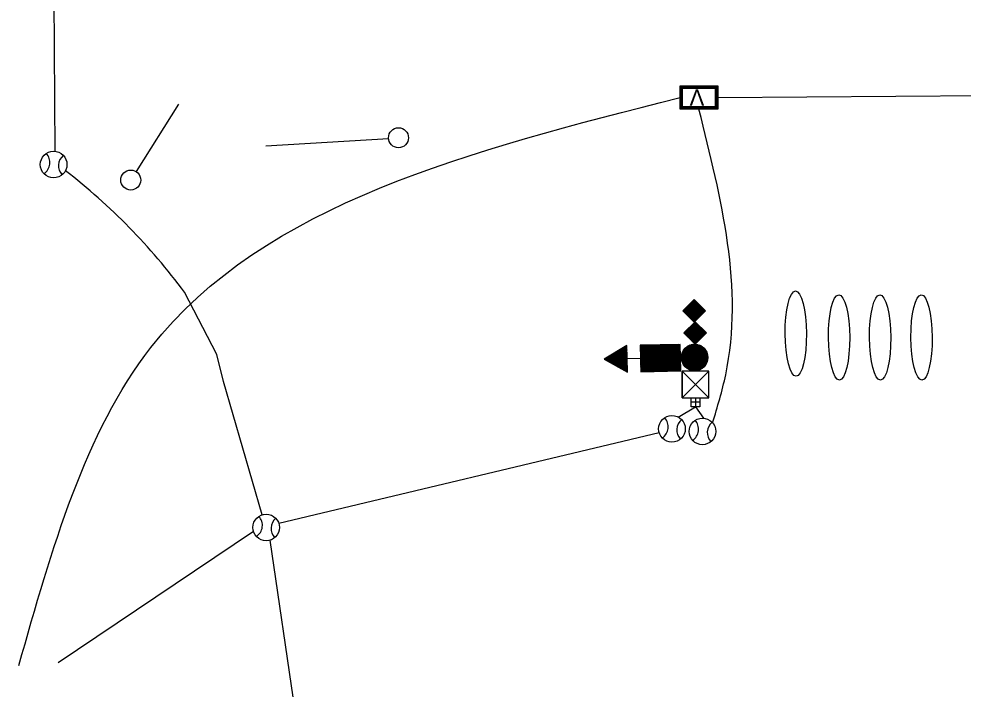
# Model space of a CAD drawing. Extents: x 584850 to 602551, y 145475 to 158627.
# Drawn here: x 594064.4 to 594348.1, y 154200.4 to 154401.9 of the extents above; entities that cross this region are included whole.
import ezdxf

# ---------------------------------------------------------------- set-up
doc = ezdxf.new("R2010")
doc.units = 0
for name, color, linetype in [('B_MISC', 7, 'Continuous'), ('Default', 7, 'Continuous'), ('E_RDWY', 7, 'Continuous')]:
    doc.layers.add(name, color=color, linetype=linetype)

# ---------------------------------------------------------------- blocks, each defined once
blk = doc.blocks.new('PB24X42')
at = {"layer": 'E_RDWY'}
blk.add_circle((0, 0), 2, dxfattribs=at)
for centre, start, end in [((-2.59, 0.09), 308.3742, 47.6044), ((2.73, 0.07), 134.4184, 228.4474)]:
    blk.add_arc(centre, 2, start, end, dxfattribs=at)

msp = doc.modelspace()

# ---------------------------------------------------------------- linework, layer by layer
at = {"layer": 'B_MISC'}
for p, q in [((594074.49, 154479.93), (594075.15, 154362.09)), ((594274.39, 154378.27), (594437.1, 154379.42)), ((594123.87, 154301.05), (594114.16, 154319.71)), ((594125.91, 154292.88), (594123.87, 154301.05)), ((594137.5, 154252.82), (594125.91, 154292.88)), ((594262.48, 154282.2), (594267.68, 154285.29)), ((594267.68, 154285.29), (594270.14, 154281.87)), ((594256.83, 154277.44), (594142.52, 154250.21)), ((594134.89, 154247.8), (594076.18, 154208.26)), ((594194.8, 153867.11), (594139.91, 154245.19))]:
    msp.add_line(p, q, dxfattribs=at)
msp.add_arc((593965.3, 154209.77), 185.05, 36.4483, 52.3419, dxfattribs=at)
for points in [[(594064.37, 154207.47), (594104.06, 154303.13), (594263.09, 154378.27)], [(594272.86, 154280.46), (594276.79, 154294.91), (594268.74, 154374.75)]]:
    msp.add_spline(points, degree=3, dxfattribs=at)
at = {"layer": 'Default'}
for p, q in [((594112.38, 154376.3), (594099.59, 154355.99)), ((594138.54, 154363.7), (594175.47, 154365.99))]:
    msp.add_line(p, q, dxfattribs=at)
for centre in [(594178.46, 154366.18), (594097.99, 154353.46)]:
    msp.add_circle(centre, 3, dxfattribs=at)
at = {"layer": 'E_RDWY'}
for p, q in [((594265.56, 154315.83), (594265.56, 154312.5)), ((594265.56, 154315.83), (594269.01, 154315.83)), ((594265.84, 154316.12), (594265.84, 154312.21)), ((594265.84, 154316.12), (594268.72, 154316.12)), ((594266.13, 154316.41), (594266.13, 154311.93)), ((594266.13, 154316.41), (594268.44, 154316.41)), ((594266.42, 154316.7), (594266.42, 154311.64)), ((594266.42, 154316.7), (594268.15, 154316.7)), ((594266.71, 154316.99), (594266.71, 154311.35)), ((594266.71, 154316.99), (594267.86, 154316.99)), ((594267, 154317.27), (594267, 154311.06)), ((594267, 154317.27), (594267.57, 154317.27)), ((594267.28, 154317.56), (594267.28, 154310.77)), ((594267.57, 154317.27), (594267.57, 154311.06)), ((594267.86, 154316.99), (594267.86, 154311.35)), ((594268.15, 154316.7), (594268.15, 154311.64)), ((594268.44, 154316.41), (594268.44, 154311.93)), ((594268.72, 154316.12), (594268.72, 154312.21)), ((594269.01, 154315.83), (594269.01, 154312.5)), ((594263.95, 154314.11), (594270.62, 154314.11)), ((594264.12, 154314.39), (594264.12, 154313.94)), ((594264.12, 154314.39), (594270.45, 154314.39)), ((594264.24, 154313.82), (594270.33, 154313.82)), ((594264.4, 154314.68), (594264.4, 154313.65)), ((594264.4, 154314.68), (594270.16, 154314.68)), ((594264.53, 154313.53), (594270.04, 154313.53)), ((594264.69, 154314.97), (594264.69, 154313.37)), ((594264.69, 154314.97), (594269.88, 154314.97)), ((594264.82, 154313.24), (594269.75, 154313.24)), ((594264.98, 154315.26), (594264.98, 154313.08)), ((594264.98, 154315.26), (594269.59, 154315.26)), ((594265.1, 154312.95), (594269.46, 154312.95)), ((594265.27, 154315.55), (594265.27, 154312.79)), ((594265.27, 154315.55), (594269.3, 154315.55)), ((594269.3, 154315.55), (594269.3, 154312.79)), ((594269.59, 154315.26), (594269.59, 154313.08)), ((594269.88, 154314.97), (594269.88, 154313.37)), ((594270.16, 154314.68), (594270.16, 154313.65)), ((594270.45, 154314.39), (594270.45, 154313.94)), ((594265.39, 154312.67), (594269.18, 154312.67)), ((594265.68, 154312.38), (594268.89, 154312.38)), ((594265.97, 154312.09), (594268.6, 154312.09)), ((594266.26, 154311.8), (594268.31, 154311.8)), ((594266.54, 154311.51), (594268.02, 154311.51)), ((594266.71, 154310), (594266.71, 154304.94)), ((594266.71, 154310), (594268.44, 154310)), ((594266.83, 154311.23), (594267.74, 154311.23)), ((594267, 154310.29), (594267, 154304.65)), ((594267, 154310.29), (594268.15, 154310.29)), ((594267.12, 154310.94), (594267.45, 154310.94)), ((594267.28, 154310.58), (594267.28, 154304.37)), ((594267.28, 154310.58), (594267.86, 154310.58)), ((594267.57, 154310.87), (594267.57, 154304.08)), ((594267.86, 154310.58), (594267.86, 154304.37)), ((594268.15, 154310.29), (594268.15, 154304.65)), ((594268.44, 154310), (594268.44, 154304.94)), ((594264.24, 154307.41), (594270.9, 154307.41)), ((594264.4, 154307.7), (594264.4, 154307.25)), ((594264.4, 154307.7), (594270.74, 154307.7)), ((594264.69, 154307.99), (594264.69, 154306.96)), ((594264.69, 154307.99), (594270.45, 154307.99)), ((594264.98, 154308.28), (594264.98, 154306.67)), ((594264.98, 154308.28), (594270.16, 154308.28)), ((594265.27, 154308.56), (594265.27, 154306.38)), ((594265.27, 154308.56), (594269.88, 154308.56)), ((594265.56, 154308.85), (594265.56, 154306.09)), ((594265.56, 154308.85), (594269.59, 154308.85)), ((594265.84, 154309.14), (594265.84, 154305.81)), ((594265.84, 154309.14), (594269.3, 154309.14)), ((594266.13, 154309.43), (594266.13, 154305.52)), ((594266.13, 154309.43), (594269.01, 154309.43)), ((594266.42, 154309.72), (594266.42, 154305.23)), ((594266.42, 154309.72), (594268.72, 154309.72)), ((594268.72, 154309.72), (594268.72, 154305.23)), ((594269.01, 154309.43), (594269.01, 154305.52)), ((594269.3, 154309.14), (594269.3, 154305.81)), ((594269.59, 154308.85), (594269.59, 154306.09)), ((594269.88, 154308.56), (594269.88, 154306.38)), ((594270.16, 154308.28), (594270.16, 154306.67)), ((594270.45, 154307.99), (594270.45, 154306.96)), ((594270.74, 154307.7), (594270.74, 154307.25)), ((594264.53, 154307.12), (594270.62, 154307.12)), ((594264.82, 154306.84), (594270.33, 154306.84)), ((594265.1, 154306.55), (594270.04, 154306.55)), ((594265.39, 154306.26), (594269.75, 154306.26)), ((594265.68, 154305.97), (594269.46, 154305.97)), ((594265.97, 154305.68), (594269.18, 154305.68)), ((594266.26, 154305.4), (594268.89, 154305.4)), ((594266.54, 154305.11), (594268.6, 154305.11)), ((594266.83, 154304.82), (594268.31, 154304.82)), ((594267.12, 154304.53), (594268.02, 154304.53)), ((594241.16, 154299.08), (594243.46, 154301.48)), ((594241.38, 154298.96), (594244.26, 154301.96)), ((594241.6, 154298.84), (594245.05, 154302.44)), ((594241.81, 154298.72), (594245.85, 154302.92)), ((594242.03, 154298.61), (594246.64, 154303.41)), ((594242.25, 154298.49), (594247.1, 154303.54)), ((594242.47, 154298.37), (594247.11, 154303.2)), ((594242.68, 154298.25), (594247.12, 154302.86)), ((594242.9, 154298.13), (594247.12, 154302.52)), ((594243.12, 154298.01), (594247.13, 154302.18)), ((594243.34, 154297.89), (594247.14, 154301.85)), ((594247.22, 154297.9), (594243.48, 154301.49)), ((594243.55, 154297.77), (594247.15, 154301.51)), ((594247.21, 154298.24), (594243.69, 154301.62)), ((594247.2, 154298.58), (594243.9, 154301.75)), ((594247.2, 154298.92), (594244.12, 154301.88)), ((594247.19, 154299.26), (594244.33, 154302.01)), ((594247.18, 154299.6), (594244.54, 154302.14)), ((594247.18, 154299.94), (594244.75, 154302.26)), ((594247.17, 154300.28), (594244.97, 154302.39)), ((594247.16, 154300.62), (594245.18, 154302.52)), ((594247.16, 154300.96), (594245.39, 154302.65)), ((594247.15, 154301.3), (594245.6, 154302.78)), ((594247.14, 154301.64), (594245.82, 154302.91)), ((594247.14, 154301.97), (594246.03, 154303.04)), ((594247.13, 154302.31), (594246.24, 154303.17)), ((594247.12, 154302.65), (594246.46, 154303.29)), ((594247.11, 154302.99), (594246.67, 154303.42)), ((594247.11, 154303.33), (594246.88, 154303.55)), ((594247.1, 154303.67), (594247.09, 154303.68)), ((594251.1, 154303.61), (594251.29, 154303.81)), ((594259.07, 154295.96), (594251.1, 154303.61)), ((594251.11, 154303.27), (594251.63, 154303.81)), ((594258.73, 154295.96), (594251.11, 154303.27)), ((594251.12, 154302.59), (594252.31, 154303.83)), ((594251.12, 154302.93), (594251.97, 154303.82)), ((594258.39, 154295.95), (594251.12, 154302.93)), ((594258.05, 154295.94), (594251.12, 154302.59)), ((594251.13, 154302.25), (594252.65, 154303.83)), ((594257.71, 154295.94), (594251.13, 154302.25)), ((594251.14, 154301.57), (594253.33, 154303.85)), ((594251.14, 154301.91), (594252.99, 154303.84)), ((594257.37, 154295.93), (594251.14, 154301.91)), ((594257.03, 154295.92), (594251.14, 154301.57)), ((594251.15, 154301.23), (594253.67, 154303.86)), ((594251.16, 154300.56), (594254.35, 154303.87)), ((594251.16, 154300.89), (594254.01, 154303.86)), ((594251.17, 154300.22), (594254.69, 154303.88)), ((594251.18, 154299.88), (594255.02, 154303.88)), ((594251.19, 154299.2), (594255.7, 154303.9)), ((594251.19, 154299.54), (594255.36, 154303.89)), ((594251.2, 154298.86), (594256.04, 154303.9)), ((594251.21, 154298.18), (594256.72, 154303.92)), ((594251.21, 154298.52), (594256.38, 154303.91)), ((594251.22, 154297.84), (594257.06, 154303.92)), ((594251.23, 154297.16), (594257.74, 154303.94)), ((594251.23, 154297.5), (594257.4, 154303.93)), ((594251.24, 154296.82), (594258.08, 154303.95)), ((594259.41, 154295.97), (594251.24, 154303.81)), ((594251.25, 154296.14), (594258.76, 154303.96)), ((594251.25, 154296.48), (594258.42, 154303.95)), ((594251.26, 154295.8), (594259.1, 154303.97)), ((594259.75, 154295.98), (594251.58, 154303.81)), ((594251.6, 154295.81), (594259.44, 154303.97)), ((594260.08, 154295.98), (594251.92, 154303.82)), ((594251.94, 154295.82), (594259.78, 154303.98)), ((594260.42, 154295.99), (594252.26, 154303.83)), ((594252.28, 154295.83), (594260.11, 154303.99)), ((594260.76, 154296), (594252.6, 154303.83)), ((594252.62, 154295.83), (594260.45, 154303.99)), ((594261.1, 154296.01), (594252.94, 154303.84)), ((594252.96, 154295.84), (594260.79, 154304)), ((594261.44, 154296.01), (594253.28, 154303.85)), ((594253.3, 154295.85), (594261.13, 154304.01)), ((594261.78, 154296.02), (594253.62, 154303.85)), ((594253.64, 154295.85), (594261.47, 154304.01)), ((594262.12, 154296.03), (594253.96, 154303.86)), ((594253.98, 154295.86), (594261.81, 154304.02)), ((594262.46, 154296.03), (594254.3, 154303.87)), ((594254.32, 154295.87), (594262.15, 154304.03)), ((594262.8, 154296.04), (594254.64, 154303.88)), ((594254.66, 154295.87), (594262.49, 154304.04)), ((594263.14, 154296.05), (594254.98, 154303.88)), ((594254.99, 154295.88), (594262.83, 154304.04)), ((594263.26, 154296.27), (594255.32, 154303.89)), ((594255.33, 154295.89), (594263.1, 154303.98)), ((594263.25, 154296.61), (594255.66, 154303.9)), ((594255.67, 154295.89), (594263.11, 154303.64)), ((594263.24, 154296.95), (594256, 154303.9)), ((594256.01, 154295.9), (594263.11, 154303.3)), ((594263.23, 154297.29), (594256.33, 154303.91)), ((594256.35, 154295.91), (594263.12, 154302.96)), ((594263.23, 154297.63), (594256.67, 154303.92)), ((594256.69, 154295.92), (594263.13, 154302.62)), ((594263.22, 154297.96), (594257.01, 154303.92)), ((594257.03, 154295.92), (594263.13, 154302.28)), ((594263.21, 154298.3), (594257.35, 154303.93)), ((594257.37, 154295.93), (594263.14, 154301.94)), ((594263.21, 154298.64), (594257.69, 154303.94)), ((594257.71, 154295.94), (594263.15, 154301.6)), ((594263.2, 154298.98), (594258.03, 154303.94)), ((594263.19, 154299.32), (594258.37, 154303.95)), ((594263.19, 154299.66), (594258.71, 154303.96)), ((594263.18, 154300), (594259.05, 154303.97)), ((594263.17, 154300.34), (594259.39, 154303.97)), ((594263.17, 154300.68), (594259.73, 154303.98)), ((594263.16, 154301.02), (594260.07, 154303.99)), ((594263.15, 154301.36), (594260.41, 154303.99)), ((594263.14, 154301.7), (594260.75, 154304)), ((594263.14, 154302.04), (594261.09, 154304.01)), ((594263.13, 154302.38), (594261.42, 154304.01)), ((594263.12, 154302.72), (594261.76, 154304.02)), ((594263.12, 154303.05), (594262.1, 154304.03)), ((594263.11, 154303.39), (594262.44, 154304.03)), ((594263.1, 154303.73), (594262.78, 154304.04)), ((594263.46, 154300.12), (594267.29, 154304.11)), ((594263.48, 154299.79), (594267.62, 154304.1)), ((594263.48, 154300.49), (594266.92, 154304.07)), ((594263.51, 154299.47), (594267.93, 154304.08)), ((594263.53, 154300.88), (594266.52, 154303.99)), ((594263.58, 154299.2), (594268.22, 154304.03)), ((594263.64, 154298.92), (594268.49, 154303.97)), ((594263.67, 154301.37), (594266.06, 154303.87)), ((594263.74, 154298.67), (594268.75, 154303.9)), ((594269.15, 154296.5), (594263.77, 154301.66)), ((594263.84, 154298.43), (594268.99, 154303.8)), ((594269.37, 154296.62), (594263.88, 154301.88)), ((594263.93, 154302), (594265.45, 154303.58)), ((594263.95, 154298.2), (594269.22, 154303.69)), ((594269.58, 154296.74), (594263.99, 154302.11)), ((594264.08, 154297.99), (594269.44, 154303.58)), ((594269.79, 154296.88), (594264.13, 154302.31)), ((594264.22, 154297.78), (594269.65, 154303.44)), ((594269.98, 154297.03), (594264.27, 154302.51)), ((594264.36, 154297.59), (594269.85, 154303.31)), ((594270.16, 154297.19), (594264.41, 154302.71)), ((594264.52, 154297.41), (594270.04, 154303.16)), ((594270.33, 154297.35), (594264.58, 154302.88)), ((594264.69, 154297.24), (594270.21, 154302.99)), ((594270.49, 154297.54), (594264.75, 154303.05)), ((594264.87, 154297.08), (594270.39, 154302.83)), ((594270.65, 154297.72), (594264.92, 154303.21)), ((594265.06, 154296.93), (594270.54, 154302.64)), ((594270.78, 154297.92), (594265.12, 154303.35)), ((594265.25, 154296.78), (594270.69, 154302.45)), ((594270.91, 154298.13), (594265.32, 154303.49)), ((594265.47, 154296.66), (594270.83, 154302.25)), ((594271.03, 154298.34), (594265.54, 154303.62)), ((594265.69, 154296.54), (594270.95, 154302.03)), ((594271.13, 154298.58), (594265.77, 154303.73)), ((594265.91, 154296.43), (594271.07, 154301.8)), ((594271.23, 154298.82), (594266, 154303.84)), ((594266.16, 154296.35), (594271.17, 154301.57)), ((594271.31, 154299.08), (594266.26, 154303.92)), ((594271.37, 154299.36), (594266.53, 154304)), ((594271.42, 154299.64), (594266.81, 154304.06)), ((594271.44, 154299.95), (594267.13, 154304.09)), ((594267.41, 154304.24), (594267.74, 154304.24)), ((594271.44, 154300.28), (594267.45, 154304.11)), ((594271.4, 154300.65), (594267.82, 154304.09)), ((594271.35, 154301.04), (594268.23, 154304.03)), ((594271.19, 154301.52), (594268.69, 154303.92)), ((594270.89, 154302.14), (594269.31, 154303.66)), ((594240.29, 154299.56), (594240.29, 154299.56)), ((594241.1, 154299.12), (594240.5, 154299.69)), ((594240.51, 154299.44), (594241.08, 154300.04)), ((594241.92, 154298.67), (594240.72, 154299.82)), ((594240.73, 154299.32), (594241.88, 154300.52)), ((594242.73, 154298.22), (594240.93, 154299.95)), ((594240.94, 154299.2), (594242.67, 154301)), ((594243.54, 154297.77), (594241.14, 154300.08)), ((594244.36, 154297.32), (594241.35, 154300.21)), ((594245.17, 154296.88), (594241.57, 154300.34)), ((594245.98, 154296.43), (594241.78, 154300.46)), ((594246.79, 154295.98), (594241.99, 154300.59)), ((594247.26, 154295.87), (594242.2, 154300.72)), ((594247.25, 154296.21), (594242.42, 154300.85)), ((594247.25, 154296.55), (594242.63, 154300.98)), ((594247.24, 154296.89), (594242.84, 154301.11)), ((594247.23, 154297.22), (594243.05, 154301.24)), ((594247.23, 154297.56), (594243.27, 154301.36)), ((594243.77, 154297.65), (594247.15, 154301.17)), ((594243.99, 154297.53), (594247.16, 154300.83)), ((594244.21, 154297.41), (594247.17, 154300.49)), ((594244.43, 154297.29), (594247.17, 154300.15)), ((594244.64, 154297.17), (594247.18, 154299.81)), ((594244.86, 154297.05), (594247.19, 154299.47)), ((594245.08, 154296.93), (594247.19, 154299.13)), ((594245.3, 154296.81), (594247.2, 154298.79)), ((594251.18, 154299.8), (594247.18, 154299.72)), ((594256.69, 154295.92), (594251.15, 154301.23)), ((594256.35, 154295.91), (594251.16, 154300.89)), ((594256.01, 154295.9), (594251.16, 154300.56)), ((594255.67, 154295.89), (594251.17, 154300.22)), ((594255.33, 154295.89), (594251.18, 154299.88)), ((594254.99, 154295.88), (594251.19, 154299.54)), ((594254.66, 154295.87), (594251.19, 154299.2)), ((594254.32, 154295.87), (594251.2, 154298.86)), ((594258.05, 154295.94), (594263.15, 154301.26)), ((594258.39, 154295.95), (594263.16, 154300.92)), ((594258.73, 154295.96), (594263.17, 154300.58)), ((594259.07, 154295.96), (594263.17, 154300.24)), ((594259.41, 154295.97), (594263.18, 154299.9)), ((594259.75, 154295.98), (594263.19, 154299.56)), ((594260.08, 154295.98), (594263.2, 154299.22)), ((594260.42, 154295.99), (594263.2, 154298.89)), ((594267.79, 154296.14), (594263.46, 154300.29)), ((594267.45, 154296.13), (594263.47, 154299.95)), ((594267.09, 154296.14), (594263.49, 154299.59)), ((594268.09, 154296.18), (594263.5, 154300.59)), ((594268.38, 154296.24), (594263.53, 154300.89)), ((594266.68, 154296.2), (594263.58, 154299.18)), ((594268.65, 154296.31), (594263.6, 154301.15)), ((594268.9, 154296.4), (594263.68, 154301.41)), ((594266.19, 154296.34), (594263.72, 154298.71)), ((594266.41, 154296.26), (594271.26, 154301.31)), ((594266.69, 154296.2), (594271.34, 154301.05)), ((594266.98, 154296.16), (594271.39, 154300.75)), ((594267.28, 154296.13), (594271.43, 154300.45)), ((594267.62, 154296.13), (594271.44, 154300.11)), ((594267.98, 154296.16), (594271.43, 154299.76)), ((594268.39, 154296.24), (594271.36, 154299.34)), ((594268.87, 154296.39), (594271.24, 154298.86)), ((594245.51, 154296.69), (594247.21, 154298.45)), ((594245.73, 154296.57), (594247.21, 154298.11)), ((594245.95, 154296.45), (594247.22, 154297.77)), ((594246.17, 154296.33), (594247.23, 154297.43)), ((594246.38, 154296.21), (594247.24, 154297.09)), ((594246.6, 154296.09), (594247.24, 154296.76)), ((594246.82, 154295.97), (594247.25, 154296.42)), ((594247.04, 154295.85), (594247.26, 154296.08)), ((594253.98, 154295.86), (594251.21, 154298.52)), ((594253.64, 154295.85), (594251.21, 154298.18)), ((594253.3, 154295.85), (594251.22, 154297.84)), ((594252.96, 154295.84), (594251.23, 154297.5)), ((594252.62, 154295.83), (594251.23, 154297.16)), ((594252.28, 154295.83), (594251.24, 154296.82)), ((594251.94, 154295.82), (594251.25, 154296.48)), ((594251.6, 154295.81), (594251.25, 154296.14)), ((594260.76, 154296), (594263.21, 154298.55)), ((594261.1, 154296.01), (594263.22, 154298.21)), ((594261.44, 154296.01), (594263.22, 154297.87)), ((594261.78, 154296.02), (594263.23, 154297.53)), ((594262.12, 154296.03), (594263.24, 154297.19)), ((594262.46, 154296.03), (594263.24, 154296.85)), ((594262.8, 154296.04), (594263.25, 154296.51)), ((594263.14, 154296.05), (594263.26, 154296.17)), ((594271.74, 154288.02), (594263.72, 154296.01)), ((594263.74, 154288.01), (594271.72, 154296.02)), ((594265.56, 154296.61), (594264.02, 154298.09)), ((594269.48, 154296.69), (594270.97, 154298.24)), ((594247.25, 154295.73), (594247.26, 154295.74)), ((594267.69, 154287.99), (594267.68, 154285.29)), ((594268.97, 154286.64), (594266.4, 154286.65))]:
    msp.add_line(p, q, dxfattribs=at)
for points in [[(594274.39, 154374.75), (594263.09, 154374.75), (594263.09, 154381.8), (594274.39, 154381.8)], [(594274.14, 154375), (594263.34, 154375), (594263.34, 154381.55), (594274.14, 154381.55)], [(594273.89, 154375.25), (594263.59, 154375.25), (594263.59, 154381.3), (594273.89, 154381.3)], [(594273.64, 154375.5), (594263.84, 154375.5), (594263.84, 154381.05), (594273.64, 154381.05)], [(594270.68, 154314.17), (594267.28, 154310.77), (594263.89, 154314.17), (594267.28, 154317.56)], [(594270.97, 154307.47), (594267.57, 154304.08), (594264.18, 154307.47), (594267.57, 154310.87)], [(594247.26, 154295.72), (594247.1, 154303.68), (594240.29, 154299.56)], [(594263.1, 154304.05), (594251.1, 154303.8), (594251.26, 154295.8), (594263.26, 154296.05)], [(594271.74, 154288.02), (594271.72, 154296.02), (594263.72, 154296.01), (594263.74, 154288.01)], [(594263.72, 154296.01), (594267.73, 154292.01), (594263.74, 154288.01)], [(594271.72, 154296.02), (594267.73, 154292.01), (594271.74, 154288.02)], [(594266.41, 154288), (594268.98, 154287.99), (594268.97, 154285.28), (594266.4, 154285.29)]]:
    msp.add_lwpolyline(points, close=True, dxfattribs=at)
msp.add_circle((594267.45, 154300.12), 4, dxfattribs=at)
for centre in [(594297.86, 154307.28), (594310.86, 154306.13), (594323.2, 154306.13), (594335.65, 154306.13)]:
    msp.add_ellipse(centre, major_axis=(0.1, -12.82), ratio=0.249166, dxfattribs=at)

# ---------------------------------------------------------------- block references
at = {"layer": 'E_RDWY', "xscale": 2, "yscale": 2.0000000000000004, "rotation": -4.918194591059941}
for p in [(594074.81, 154358.11), (594260.64, 154278.65), (594269.79, 154277.88), (594138.7, 154249)]:
    msp.add_blockref('PB24X42', p, dxfattribs=at)

# ---------------------------------------------------------------- texts
at = {"layer": 'E_RDWY'}
msp.add_text('V', height=4.96, rotation=180, dxfattribs=at).set_placement((594270.36, 154380.75))

doc.saveas('drawing.dxf')
